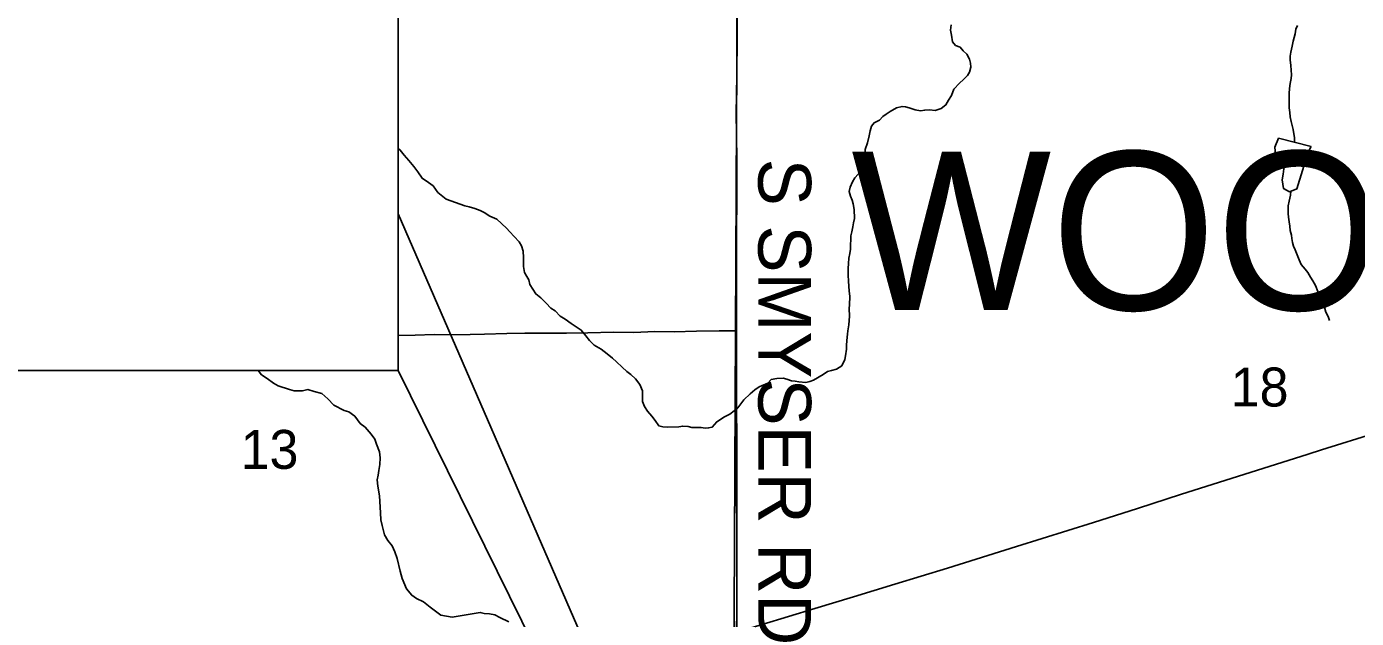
# Model space of a CAD drawing. Extents: x 0 to 34, y 0 to 22.
# Drawn here: x 5.015 to 6.446, y 18.505 to 19.142 of the extents above; entities that cross this region are included whole.
import ezdxf

# ---------------------------------------------------------------- set-up
doc = ezdxf.new("R2010")
doc.units = 0
for name, color, linetype in [('Default', 7, 'Continuous'), ('GM_X_Minor_Lake', 7, 'Continuous'), ('GM_X_Minor_River', 7, 'Continuous'), ('GM_X_Section', 7, 'Continuous'), ('GM_X_Section_Text', 7, 'Continuous'), ('GM_X_State_Route', 7, 'Continuous'), ('GM_X_Township_Road', 7, 'Continuous'), ('GM_X_Township_Road_Text', 7, 'Continuous'), ('GM_X_Township_Text', 7, 'Continuous'), ('SH_Text', 7, 'Continuous')]:
    doc.layers.add(name, color=color, linetype=linetype)

msp = doc.modelspace()

# ---------------------------------------------------------------- linework, layer by layer
at = {"layer": 'Default'}
msp.add_lwpolyline([(5.415, 18.9404), (6.0271, 17.5311), (5.415, 18.772)], close=True, dxfattribs=at)
at = {"layer": 'GM_X_Minor_Lake'}
for points in [[(6.3622, 19.0218), (6.3581, 19.0123), (6.3589, 19.0047), (6.3635, 18.9998), (6.3681, 18.9918), (6.367, 18.9831), (6.3659, 18.977), (6.3675, 18.9676), (6.374, 18.9642), (6.3819, 18.9673), (6.3941, 19.0068), (6.3971, 19.0129)], [(6.3971, 19.0129), (6.3622, 19.0218)]]:
    msp.add_lwpolyline(points, dxfattribs=at)
at = {"layer": 'GM_X_Minor_River'}
for points in [[(6.0101, 19.1437), (6.0094, 19.1379), (6.0102, 19.1326), (6.0115, 19.1254), (6.0146, 19.1217)], [(6.3824, 19.1429), (6.3806, 19.1391), (6.3799, 19.1342), (6.3788, 19.13), (6.3777, 19.1262), (6.3766, 19.1208), (6.3752, 19.1143), (6.3745, 19.1102), (6.3746, 19.106), (6.3754, 19.0999), (6.3758, 19.095), (6.3759, 19.09), (6.3756, 19.0859), (6.3745, 19.0805), (6.3738, 19.0752), (6.3735, 19.0699), (6.3737, 19.0543), (6.3742, 19.0494), (6.3746, 19.0448), (6.3758, 19.0399), (6.3766, 19.0353), (6.3778, 19.0312), (6.3791, 19.0221), (6.3794, 19.0174)], [(6.0146, 19.1217), (6.0195, 19.1198), (6.023, 19.1157), (6.0269, 19.1123), (6.0296, 19.1067), (6.0308, 19.1025), (6.0312, 19.0984), (6.0298, 19.093), (6.0275, 19.0892), (6.0234, 19.0849), (6.0189, 19.0811), (6.0129, 19.0746), (6.0103, 19.0677), (6.007, 19.0627), (6.0044, 19.0577), (5.9991, 19.0539), (5.9927, 19.0515), (5.9866, 19.0522), (5.9816, 19.0521), (5.9771, 19.0513), (5.9714, 19.0523), (5.9649, 19.0545), (5.961, 19.0556), (5.9572, 19.056), (5.9512, 19.0544), (5.9444, 19.0505), (5.9402, 19.0478), (5.9365, 19.045), (5.9327, 19.0412), (5.927, 19.0385), (5.9244, 19.0346), (5.923, 19.0297), (5.9219, 19.0243), (5.9201, 19.0167), (5.9175, 19.0095), (5.9172, 19.0049), (5.9169, 19), (5.9166, 18.9939), (5.9148, 18.9878), (5.9099, 18.9831), (5.9065, 18.9793), (5.9039, 18.9747), (5.9013, 18.969), (5.9002, 18.9644), (5.9018, 18.9595), (5.9034, 18.9553), (5.9046, 18.9512), (5.9058, 18.9451), (5.9059, 18.9356), (5.9049, 18.9307), (5.9042, 18.9265), (5.9031, 18.9211), (5.902, 18.9166), (5.902, 18.9128), (5.9017, 18.9071), (5.9018, 18.9025), (5.9011, 18.8979), (5.9, 18.8926), (5.8997, 18.8869), (5.899, 18.8816), (5.8991, 18.874), (5.8996, 18.8683), (5.9, 18.8622), (5.9001, 18.8577), (5.9009, 18.8516), (5.9007, 18.8425), (5.9003, 18.8387), (5.9005, 18.8303), (5.8998, 18.8212), (5.8988, 18.8147), (5.8984, 18.8109), (5.8978, 18.8041), (5.8974, 18.7987), (5.8975, 18.795), (5.8964, 18.7877), (5.8957, 18.7839), (5.8924, 18.777), (5.8867, 18.7735), (5.8814, 18.7719), (5.8769, 18.7707), (5.8724, 18.7676), (5.8618, 18.7614), (5.858, 18.7599), (5.8538, 18.759), (5.8462, 18.7597), (5.842, 18.7604), (5.8382, 18.7607), (5.8333, 18.7626), (5.8291, 18.7636), (5.8226, 18.7632), (5.8165, 18.7623), (5.8128, 18.7581), (5.8033, 18.7542), (5.7988, 18.7511), (5.7939, 18.7468), (5.7868, 18.7403), (5.7838, 18.7361), (5.7804, 18.7318), (5.7767, 18.7284), (5.7718, 18.7249), (5.7661, 18.7222)], [(5.487, 18.949), (5.4667, 18.9561), (5.4579, 18.9633), (5.4526, 18.9705), (5.4476, 18.9743), (5.4408, 18.9788), (5.4362, 18.9856), (5.432, 18.9913), (5.4266, 18.9978), (5.4217, 19.0034), (5.4174, 19.0091), (5.415, 19.0107)], [(6.3753, 18.9647), (6.3749, 18.9605), (6.3735, 18.954), (6.3724, 18.9491), (6.3725, 18.9407), (6.373, 18.9369), (6.3734, 18.932), (6.3742, 18.9271), (6.3747, 18.9225), (6.3759, 18.9176), (6.3763, 18.9138), (6.3771, 18.9096), (6.3783, 18.9055), (6.3799, 18.9017), (6.3822, 18.8964), (6.3842, 18.8911), (6.3865, 18.8858), (6.3908, 18.8809), (6.3935, 18.8772), (6.3966, 18.8723), (6.3989, 18.8685), (6.4017, 18.8632), (6.4044, 18.8568), (6.4068, 18.853), (6.4083, 18.8485), (6.4095, 18.8443), (6.4119, 18.8387), (6.4131, 18.8345), (6.4154, 18.83), (6.417, 18.8258)], [(5.7661, 18.7222), (5.7578, 18.7167), (5.7529, 18.711), (5.7491, 18.7102), (5.7453, 18.7097), (5.7411, 18.7104), (5.7358, 18.7104), (5.7309, 18.7107), (5.7271, 18.7118), (5.7213, 18.7121), (5.7172, 18.7113), (5.7046, 18.7111), (5.6997, 18.7114), (5.6955, 18.7125), (5.6916, 18.7181), (5.6881, 18.7226), (5.6835, 18.7283), (5.68, 18.7332), (5.678, 18.7385), (5.6779, 18.7502), (5.6751, 18.757), (5.6705, 18.763), (5.6655, 18.7675), (5.6612, 18.7709), (5.6559, 18.7754), (5.6501, 18.7814), (5.6455, 18.7851), (5.6401, 18.79), (5.6336, 18.7948), (5.6259, 18.7993), (5.6209, 18.8042), (5.617, 18.8091), (5.612, 18.8154), (5.6055, 18.8195), (5.6012, 18.8225), (5.5947, 18.827), (5.5894, 18.8303), (5.584, 18.836), (5.5794, 18.8389), (5.5743, 18.8442), (5.5686, 18.8502), (5.5632, 18.8543), (5.5566, 18.8645), (5.5558, 18.8694), (5.5534, 18.8732), (5.5511, 18.8773), (5.5499, 18.8838), (5.5498, 18.8876), (5.5501, 18.8933), (5.5497, 18.9001), (5.5477, 18.9061), (5.5453, 18.9103), (5.5399, 18.9159), (5.5353, 18.9212), (5.5315, 18.9249), (5.5211, 18.9347), (5.5138, 18.938), (5.5077, 18.9417), (5.5034, 18.9439), (5.4977, 18.9461), (5.4916, 18.9479), (5.487, 18.949)], [(5.4733, 18.5064), (5.4611, 18.5086), (5.4553, 18.5131), (5.4496, 18.5173), (5.4424, 18.5229), (5.4348, 18.5267), (5.4298, 18.5301), (5.4241, 18.5369), (5.4195, 18.5483), (5.4172, 18.5559), (5.4141, 18.5696), (5.4117, 18.5768), (5.4087, 18.5832), (5.4041, 18.5889), (5.4003, 18.595), (5.3979, 18.6052), (5.3964, 18.6113), (5.3963, 18.6189), (5.3951, 18.6372), (5.3932, 18.6474), (5.3924, 18.6543), (5.3935, 18.6592), (5.3942, 18.6642), (5.3953, 18.6706), (5.3957, 18.6779), (5.3952, 18.6843), (5.3918, 18.6927), (5.3899, 18.698), (5.386, 18.7033), (5.3795, 18.7109), (5.3742, 18.715), (5.3685, 18.7226), (5.362, 18.7275), (5.3571, 18.729), (5.346, 18.7347), (5.3395, 18.7415), (5.3331, 18.7471), (5.3247, 18.7494), (5.3179, 18.7513), (5.3122, 18.7501), (5.3034, 18.7501), (5.2981, 18.7516), (5.286, 18.7553), (5.281, 18.7583), (5.2741, 18.7632), (5.2681, 18.7674), (5.2645, 18.772)], [(5.5076, 18.5105), (5.5034, 18.5116), (5.4733, 18.5064)], [(5.5343, 18.5014), (5.5244, 18.5062), (5.519, 18.5092), (5.5133, 18.5102), (5.5076, 18.5105)]]:
    msp.add_lwpolyline(points, dxfattribs=at)
at = {"layer": 'GM_X_Section'}
for points in [[(4.7796, 18.772), (4.7762, 18.2959), (5.7756, 18.2855), (5.7801, 19.2683), (5.7798, 19.3134), (5.415, 19.3104), (5.415, 18.772)], [(5.7801, 19.2683), (6.9057, 19.2783), (6.9105, 18.2623), (5.7758, 18.2578), (5.7756, 18.2855)]]:
    msp.add_lwpolyline(points, close=True, dxfattribs=at)
at = {"layer": 'GM_X_State_Route'}
for points in [[(6.4082, 18.6865), (6.4681, 18.7052)], [(5.7794, 18.4904), (5.8068, 18.4986), (5.8633, 18.5157), (5.9049, 18.5284), (5.9494, 18.5421), (6.0059, 18.5594), (6.0801, 18.5824), (6.163, 18.6084), (6.2104, 18.6235), (6.2577, 18.6388), (6.311, 18.6557), (6.3939, 18.682), (6.4082, 18.6865)]]:
    msp.add_lwpolyline(points, dxfattribs=at)
at = {"layer": 'GM_X_Township_Road'}
for points in [[(5.7792, 18.8145), (5.7791, 18.8738), (5.7792, 18.9141), (5.7793, 18.9638), (5.7793, 18.9979), (5.7791, 19.0259), (5.779, 19.0476), (5.7795, 19.088), (5.7798, 19.1314), (5.7798, 19.1594), (5.7799, 19.1811), (5.78, 19.1966), (5.7801, 19.209), (5.7802, 19.2276), (5.7802, 19.2463), (5.7803, 19.2587), (5.7805, 19.2684)], [(5.7796, 19.1599), (5.7796, 19.132), (5.7793, 19.0885), (5.7788, 19.0481), (5.7789, 19.0264), (5.7791, 18.9985), (5.779, 18.9644), (5.779, 18.9147), (5.7789, 18.8743), (5.779, 18.8151), (5.779, 18.7967), (5.7788, 18.7595), (5.779, 18.7281), (5.7791, 18.7036), (5.7792, 18.657), (5.7793, 18.5794), (5.7793, 18.5142), (5.7792, 18.4909)], [(5.7792, 18.4909), (5.7793, 18.5142), (5.7793, 18.5794), (5.7792, 18.657), (5.7791, 18.7036), (5.779, 18.7281), (5.7788, 18.7595), (5.779, 18.7967), (5.779, 18.8151), (5.7789, 18.8743), (5.779, 18.9147), (5.779, 18.9644), (5.7791, 18.9985), (5.7789, 19.0264), (5.7788, 19.0481), (5.7793, 19.0885), (5.7796, 19.132), (5.7796, 19.1599)], [(5.415, 18.8095), (5.4333, 18.8098), (5.4539, 18.8105), (5.4712, 18.8104), (5.4925, 18.8108), (5.508, 18.811), (5.532, 18.8116), (5.5515, 18.8119), (5.5759, 18.8122), (5.5962, 18.812), (5.6192, 18.8125), (5.6469, 18.813), (5.6685, 18.8128), (5.6913, 18.8137), (5.712, 18.8136), (5.736, 18.8143), (5.7603, 18.8144), (5.7712, 18.8145), (5.7776, 18.8145), (5.7792, 18.8145)], [(5.7794, 18.4904), (5.7795, 18.5137), (5.7795, 18.5789), (5.7794, 18.6565), (5.7793, 18.703), (5.7792, 18.7276), (5.779, 18.7589), (5.7792, 18.7962), (5.7792, 18.8145)]]:
    msp.add_lwpolyline(points, dxfattribs=at)
at = {"layer": 'SH_Text'}
msp.add_lwpolyline([(3.1951, 19.4891), (5.415, 19.4891), (5.415, 18.772), (3.1951, 18.772)], close=True, dxfattribs=at)

# ---------------------------------------------------------------- texts
at = {"layer": 'GM_X_Section_Text'}
for s, p in [('18', (6.3106, 18.7332)), ('13', (5.2456, 18.6661))]:
    msp.add_text(s, height=0.04186, rotation=0, dxfattribs=at).set_placement(p)
at = {"layer": 'GM_X_Township_Road_Text'}
msp.add_text('S SMYSER RD', height=0.056818, rotation=270, dxfattribs=at).set_placement((5.8025, 18.9998))
at = {"layer": 'GM_X_Township_Text'}
msp.add_text('WOOSTER', height=0.17045, rotation=0, dxfattribs=at).set_placement((5.9025, 18.837))

doc.saveas('drawing.dxf')
